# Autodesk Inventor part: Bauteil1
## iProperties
Created: 2010-03
Part Number: Bauteil1
Material: Standard
Document SubType Name: Blech
Designer: Schwandt
Density: 1 g/cm^3
Flat Pattern Width: 17.4316 cm
Flat Pattern Length: 16.8139 cm
Flat Pattern Area: 293.093 cm^2
Sheet Metal Rule: Standard_mm
Author: Schwandt
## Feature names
1. Grobblech1
2. Grobblech2
3. Biegung1
4. Grobblech3
5. Biegung2
6. Grobblech4
7. Biegung3
8. Grobblech5
9. Biegung4
